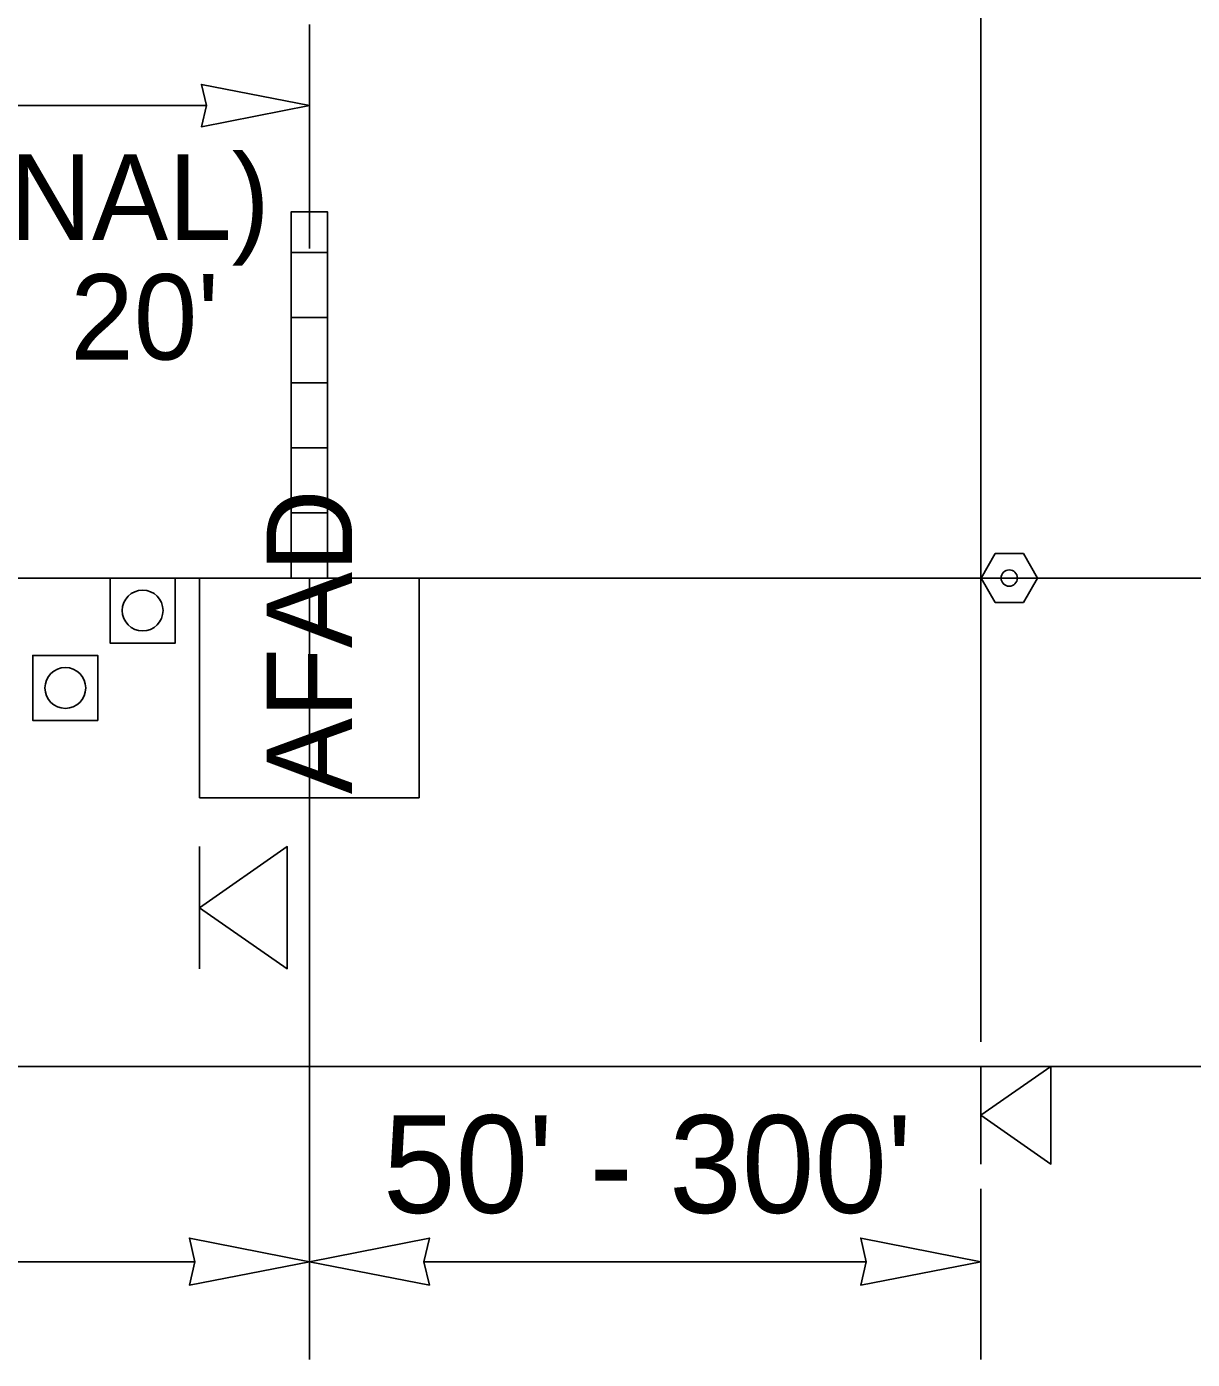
# Model space of a CAD drawing. Extents: x 99999.1 to 100095.7, y 99995 to 100010.7.
# Drawn here: x 100044.045 to 100045, y 100005.492 to 100006.584 of the extents above; entities that cross this region are included whole.
import ezdxf

# ---------------------------------------------------------------- set-up
doc = ezdxf.new("R2010")
doc.units = 0
for name, color, linetype in [('RD_ED_ShoulderPavedEdge', 7, 'Continuous'), ('RD_MK_LineEdgeWhite', 7, 'Continuous'), ('TR_WZ_AFAD', 7, 'Continuous'), ('TR_WZ_PortableSignMountBlk-Wht', 7, 'Continuous'), ('TR_WZ_TrafficCone', 7, 'Continuous'), ('TR_WZ_TubularMarker', 7, 'Continuous'), ('TR_WZ_WorkZoneDetails', 7, 'Continuous'), ('TR_WZ_WorkZoneTextCurrent', 7, 'Continuous')]:
    doc.layers.add(name, color=color, linetype=linetype)

msp = doc.modelspace()

# ---------------------------------------------------------------- linework, layer by layer
at = {"layer": 'RD_ED_ShoulderPavedEdge'}
msp.add_line((100040.1076, 100005.7323), (100055.6424, 100005.7323), dxfattribs=at)
at = {"layer": 'RD_MK_LineEdgeWhite'}
msp.add_line((100040.1076, 100006.1323), (100055.6424, 100006.1323), dxfattribs=at)
at = {"layer": 'TR_WZ_AFAD'}
for p, q in [((100044.2916, 100006.399), (100044.2916, 100006.4323)), ((100044.2616, 100006.399), (100044.2616, 100006.3457)), ((100044.2616, 100006.399), (100044.2766, 100006.399)), ((100044.2766, 100006.399), (100044.2916, 100006.399)), ((100044.2916, 100006.3457), (100044.2916, 100006.399)), ((100044.2616, 100006.3457), (100044.2616, 100006.2923)), ((100044.2766, 100006.3457), (100044.2616, 100006.3457)), ((100044.2916, 100006.3457), (100044.2766, 100006.3457)), ((100044.2916, 100006.2923), (100044.2916, 100006.3457)), ((100044.2616, 100006.2923), (100044.2616, 100006.239)), ((100044.2616, 100006.2923), (100044.2766, 100006.2923)), ((100044.2766, 100006.2923), (100044.2916, 100006.2923)), ((100044.2916, 100006.239), (100044.2916, 100006.2923)), ((100044.2766, 100006.239), (100044.2616, 100006.239)), ((100044.2616, 100006.239), (100044.2616, 100006.1857)), ((100044.2916, 100006.239), (100044.2766, 100006.239)), ((100044.2916, 100006.1857), (100044.2916, 100006.239)), ((100044.2616, 100006.1857), (100044.2616, 100006.1323)), ((100044.1866, 100005.9523), (100044.1866, 100006.1323)), ((100044.1866, 100006.1323), (100044.3666, 100006.1323)), ((100044.27, 100006.1323), (100044.1866, 100006.1323)), ((100044.1866, 100006.1323), (100044.1866, 100005.9523)), ((100044.2616, 100006.1323), (100044.27, 100006.1323)), ((100044.27, 100006.1323), (100044.2766, 100006.1323)), ((100044.3666, 100006.1323), (100044.3666, 100005.9523)), ((100044.3666, 100005.9523), (100044.3666, 100006.1323)), ((100044.3666, 100005.9523), (100044.1866, 100005.9523)), ((100044.1866, 100005.9523), (100044.3666, 100005.9523))]:
    msp.add_line(p, q, dxfattribs=at)
for points in [[(100044.2916, 100006.4323), (100044.2616, 100006.4323), (100044.2616, 100006.399)], [(100044.2916, 100006.1323), (100044.2916, 100006.4323), (100044.2616, 100006.4323), (100044.2616, 100006.1323)], [(100044.2916, 100006.399), (100044.2766, 100006.399), (100044.2616, 100006.399)], [(100044.2616, 100006.3457), (100044.2766, 100006.3457), (100044.2916, 100006.3457)], [(100044.2916, 100006.2923), (100044.2766, 100006.2923), (100044.2616, 100006.2923)], [(100044.2616, 100006.239), (100044.2766, 100006.239), (100044.2916, 100006.239)], [(100044.2916, 100006.1857), (100044.2766, 100006.1857), (100044.2616, 100006.1857)], [(100044.2616, 100006.1857), (100044.2766, 100006.1857), (100044.2916, 100006.1857)], [(100044.2766, 100006.1323), (100044.2833, 100006.1323), (100044.2916, 100006.1323), (100044.2916, 100006.1857)], [(100044.3666, 100006.1323), (100044.2833, 100006.1323), (100044.27, 100006.1323)]]:
    msp.add_lwpolyline(points, dxfattribs=at)
at = {"layer": 'TR_WZ_PortableSignMountBlk-Wht'}
for p, q in [((100044.1867, 100005.8123), (100044.1867, 100005.9123)), ((100044.8267, 100005.6523), (100044.8267, 100005.7323))]:
    msp.add_line(p, q, dxfattribs=at)
for points in [[(100044.1867, 100005.8622), (100044.2585, 100005.9123), (100044.2585, 100005.8123)], [(100044.8267, 100005.6923), (100044.8841, 100005.7323), (100044.8841, 100005.6523)]]:
    msp.add_lwpolyline(points, close=True, dxfattribs=at)
at = {"layer": 'TR_WZ_TrafficCone'}
for points in [[(100044.1133, 100006.1323), (100044.1667, 100006.1323), (100044.1667, 100006.079), (100044.1133, 100006.079), (100044.1133, 100006.1323)], [(100044.1133, 100006.079), (100044.1667, 100006.079), (100044.1667, 100006.1323), (100044.1133, 100006.1323), (100044.1133, 100006.079)], [(100044.05, 100006.069), (100044.1033, 100006.069), (100044.1033, 100006.0157), (100044.05, 100006.0157), (100044.05, 100006.069)], [(100044.05, 100006.0157), (100044.1033, 100006.0157), (100044.1033, 100006.069), (100044.05, 100006.069), (100044.05, 100006.0157)]]:
    msp.add_lwpolyline(points, dxfattribs=at)
for centre in [(100044.14, 100006.1057), (100044.0767, 100006.0423)]:
    msp.add_circle(centre, 0.0167, dxfattribs=at)
at = {"layer": 'TR_WZ_TubularMarker'}
msp.add_lwpolyline([(100044.8269, 100006.1323), (100044.8385, 100006.1523), (100044.8616, 100006.1523), (100044.8731, 100006.1323), (100044.8616, 100006.1123), (100044.8385, 100006.1123)], close=True, dxfattribs=at)
msp.add_lwpolyline([(100044.8385, 100006.1123), (100044.8616, 100006.1123), (100044.8731, 100006.1323), (100044.8616, 100006.1523), (100044.8385, 100006.1523), (100044.8269, 100006.1323), (100044.8385, 100006.1123)], dxfattribs=at)
msp.add_circle((100044.85, 100006.1323), 0.00667, dxfattribs=at)
at = {"layer": 'TR_WZ_WorkZoneDetails'}
for p, q in [((100044.8267, 100005.7523), (100044.8267, 100007.7323)), ((100044.2767, 100006.5857), (100044.2767, 100006.4023)), ((100044.1923, 100006.5193), (100043.761, 100006.5193)), ((100044.2767, 100006.1323), (100044.2767, 100005.4923)), ((100044.8267, 100005.4923), (100044.8267, 100005.6319)), ((100044.1829, 100005.5723), (100043.5704, 100005.5723)), ((100044.1829, 100005.5723), (100043.6204, 100005.5723)), ((100044.7329, 100005.5723), (100044.3704, 100005.5723))]:
    msp.add_line(p, q, dxfattribs=at)
for points in [[(100044.2767, 100006.5193), (100044.1882, 100006.502), (100044.1923, 100006.5193), (100044.1882, 100006.5367)], [(100044.2767, 100005.5723), (100044.1784, 100005.5916), (100044.1829, 100005.5723), (100044.1784, 100005.5531)], [(100044.2767, 100005.5723), (100044.3749, 100005.5916), (100044.3704, 100005.5723), (100044.3749, 100005.5531)], [(100044.8267, 100005.5723), (100044.7284, 100005.5916), (100044.7329, 100005.5723), (100044.7284, 100005.5531)]]:
    msp.add_lwpolyline(points, close=True, dxfattribs=at)

# ---------------------------------------------------------------- texts
at = {"layer": 'TR_WZ_AFAD'}
msp.add_text('AFAD', height=0.07, rotation=90, dxfattribs=at).set_placement((100044.3116, 100005.9553))
at = {"layer": 'TR_WZ_WorkZoneTextCurrent'}
for s, p in [('(OPTIONAL)', (100043.7085, 100006.4093)), ("20'", (100044.0807, 100006.3113))]:
    msp.add_text(s, height=0.07, dxfattribs=at).set_placement(p)
msp.add_text("50' - 300'", height=0.08, rotation=360, dxfattribs=at).set_placement((100044.3369, 100005.6123))

doc.saveas('drawing.dxf')
